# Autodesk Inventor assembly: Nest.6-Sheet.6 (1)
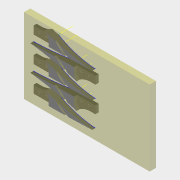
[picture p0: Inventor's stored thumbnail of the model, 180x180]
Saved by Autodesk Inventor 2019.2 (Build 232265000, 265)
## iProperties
Created: 2019-02
Part Number: Nest.6-Sheet.6 (1)
Document SubType Name: Assembly
Designer: User
Author: User
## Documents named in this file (3)
- D:\Slotmachine\Workspaces\Workspace\Cabinet\Hopper\Nest.6-Sheet.6 (1).iam
- D:\Slotmachine\Workspaces\Workspace\Cabinet\Hopper\CAM parts\STOCK Stainless Steel_Sheet.6 (1).ipt
- D:\Slotmachine\Workspaces\Workspace\Cabinet\Hopper\CAM parts\Hopper - Knife.ipt
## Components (6 placed, 2 different names)
1. STOCK Stainless Steel:1
2. Hopper - Knife:1
3. Hopper - Knife:2
4. Hopper - Knife:3
5. Hopper - Knife:4
6. Hopper - Knife:5
